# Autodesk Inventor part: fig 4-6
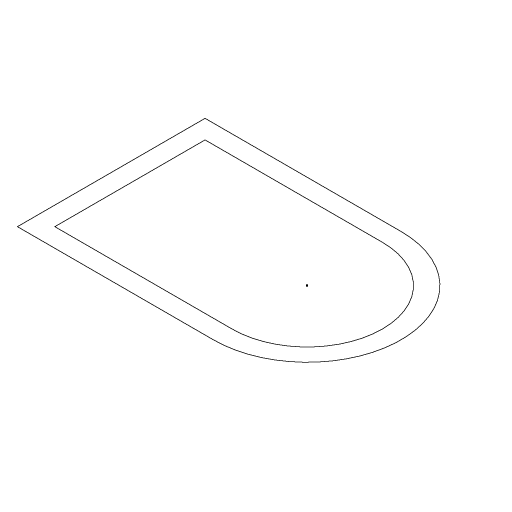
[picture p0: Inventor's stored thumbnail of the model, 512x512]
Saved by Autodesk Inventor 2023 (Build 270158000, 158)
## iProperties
Created: 2005-02
Part Number: fig 4-6
Document SubType Name: Modeling
Designer: CADCIM
Manufacturer: Standard
Standards Organization: Custom
Density: 1 g/cm^3
Material: Generic
Appearance: Default
Author: CADCIM
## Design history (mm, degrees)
sketch "Sketch1"
  geometry: L1 (12.963, 23.563)-(-25.99, 23.563); L2 (-25.99, 23.563)-(-25.99, -13.729); L3 (-25.99, -13.729)-(12.963, -13.729); L4 (-22.275, 19.848)-(12.963, 19.848); L5 (12.963, -10.014)-(-22.275, -10.014); L6 (-22.275, -10.014)-(-22.275, 19.848); A1 r 18.646 centre (12.963, 4.917) between (12.963, -13.729) and (12.963, 23.563); A2 r 14.931 centre (12.963, 4.917) between (12.963, -10.014) and (12.963, 19.848)
  constraints: 12 end point, 4 point on circle, 2 centre point, 2 parallel, 2 perpendicular, 2 tangent, 1 horizontal, 4 other
